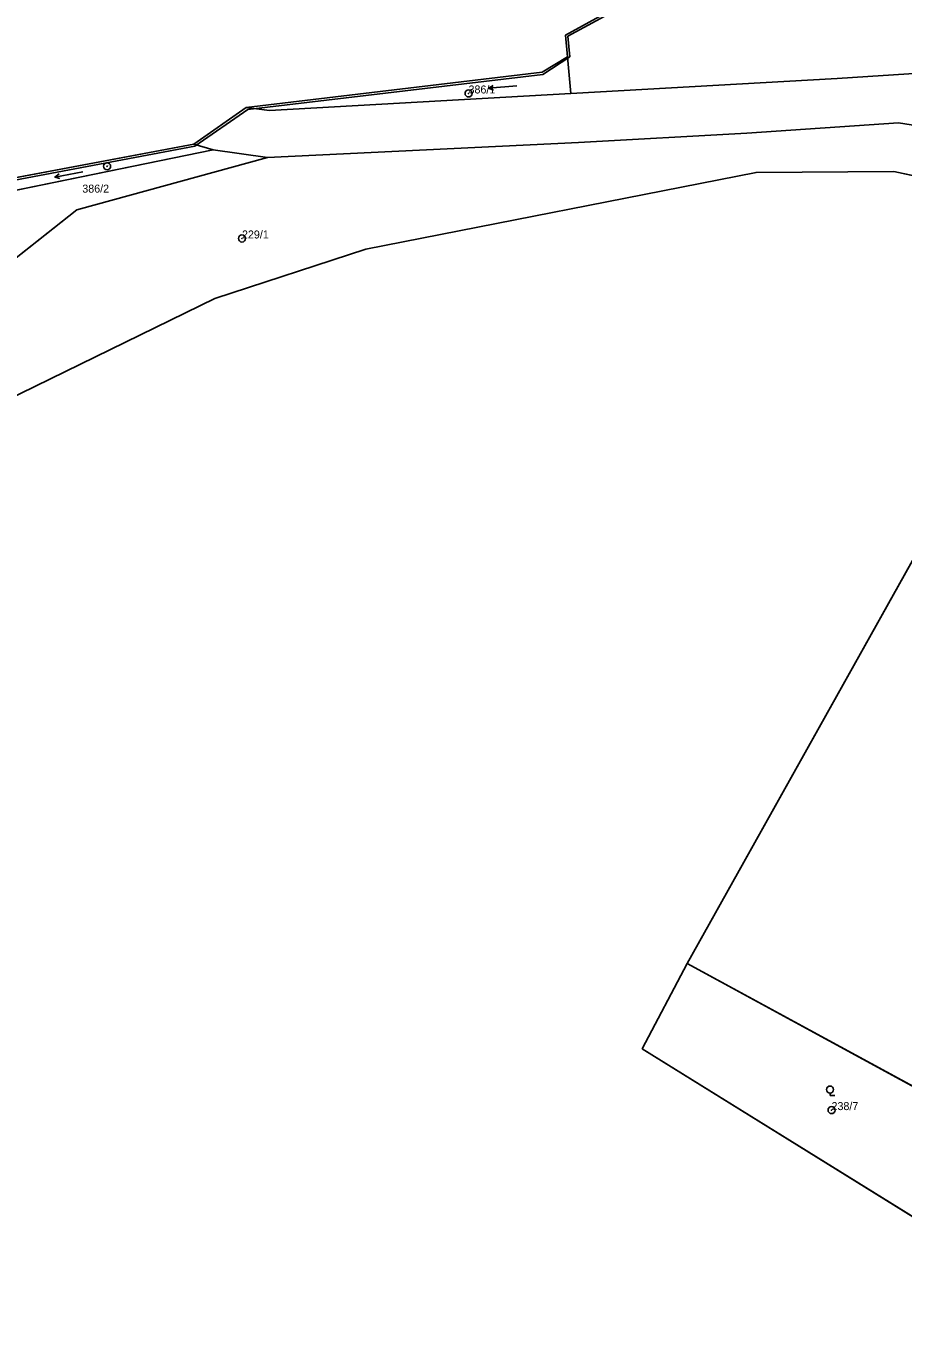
# Model space of a CAD drawing. Extents: x -652854 to -650068, y -1097661 to -1095417.
# Drawn here: x -651296.9 to -651110.6, y -1096137.1 to -1095861.8 of the extents above; entities that cross this region are included whole.
import ezdxf

# ---------------------------------------------------------------- set-up
doc = ezdxf.new("R2010")
doc.units = 0
for name, color, linetype in [('Definiční body parcel', 7, 'Continuous'), ('Hranice obcí', 7, 'Continuous'), ('Hranice parcel', 7, 'Continuous'), ('Obvody jako plochy', 7, 'Continuous'), ('Ostatní hranice', 7, 'Continuous'), ('Parcelní čísla', 7, 'Continuous'), ('Prvky pro prodl_ par_ č_', 7, 'Continuous'), ('Značky kultur', 7, 'Continuous')]:
    doc.layers.add(name, color=color, linetype=linetype)

msp = doc.modelspace()

# ---------------------------------------------------------------- linework, layer by layer
at = {"layer": 'Definiční body parcel'}
for centre, radius in [((-651202.86, -1095876.12), 0.75), ((-651202.86, -1095876.12), 0.0327), ((-651279.63, -1095891.58), 0.75), ((-651279.63, -1095891.58), 0.0327), ((-651250.98, -1095906.92), 0.75), ((-651250.98, -1095906.92), 0.0327), ((-651125.76, -1096092.04), 0.75), ((-651125.76, -1096092.04), 0.0327)]:
    msp.add_circle(centre, radius, dxfattribs=at)
at = {"layer": 'Hranice obcí'}
for p, q in [((-651182.24, -1095863.72), (-651170.03, -1095857.03)), ((-651181.83, -1095868.33), (-651182.24, -1095863.72)), ((-651187.22, -1095871.58), (-651181.83, -1095868.33)), ((-651250.06, -1095879.13), (-651187.22, -1095871.58)), ((-651261.23, -1095886.87), (-651250.06, -1095879.13)), ((-651306.87, -1095895.47), (-651261.23, -1095886.87))]:
    msp.add_line(p, q, dxfattribs=at)
at = {"layer": 'Hranice parcel'}
for p, q in [((-651181.14, -1095876.14), (-651181.83, -1095868.33)), ((-651181.14, -1095876.14), (-651124.53, -1095872.94)), ((-651124.53, -1095872.94), (-651106.05, -1095871.75)), ((-651245.11, -1095879.76), (-651181.14, -1095876.14)), ((-651250.06, -1095879.13), (-651245.11, -1095879.76)), ((-651143.77, -1095884.53), (-651111.53, -1095882.37)), ((-651111.53, -1095882.37), (-651098.01, -1095884.51)), ((-651179.53, -1095886.51), (-651143.77, -1095884.53)), ((-651304.11, -1095897.7), (-651257.1, -1095888.1)), ((-651261.23, -1095886.87), (-651257.1, -1095888.1)), ((-651257.1, -1095888.1), (-651245.57, -1095889.73)), ((-651245.57, -1095889.73), (-651179.53, -1095886.51)), ((-651245.57, -1095889.73), (-651286.04, -1095900.87)), ((-651141.79, -1095892.88), (-651224.65, -1095909.2)), ((-651112.56, -1095892.68), (-651141.79, -1095892.88)), ((-651086.96, -1095898.16), (-651112.56, -1095892.68)), ((-651326.79, -1095933.01), (-651286.04, -1095900.87)), ((-651224.65, -1095909.2), (-651256.73, -1095919.7)), ((-651256.73, -1095919.7), (-651301.18, -1095941.4)), ((-651099.24, -1095958.6), (-651156.45, -1096060.87)), ((-651156.45, -1096060.87), (-651165.97, -1096079.02)), ((-651156.45, -1096060.87), (-651088.94, -1096097.65)), ((-651165.97, -1096079.02), (-651097.64, -1096121.44))]:
    msp.add_line(p, q, dxfattribs=at)
at = {"layer": 'Obvody jako plochy'}
for points in [[(-651124.53, -1095872.94), (-651106.05, -1095871.75), (-651093.24, -1095871.75), (-651090.63, -1095871.34), (-651091.53, -1095855.39), (-651091.66, -1095853.64), (-651099.73, -1095851.59), (-651143.81, -1095850.45), (-651170.03, -1095857.03), (-651182.24, -1095863.72), (-651181.83, -1095868.33), (-651181.14, -1095876.14)], [(-651250.06, -1095879.13), (-651245.11, -1095879.76), (-651181.14, -1095876.14), (-651181.83, -1095868.33), (-651187.22, -1095871.58)], [(-651261.23, -1095886.87), (-651306.87, -1095895.47), (-651304.11, -1095897.7), (-651257.1, -1095888.1)], [(-651156.45, -1096060.87), (-651165.97, -1096079.02), (-651097.64, -1096121.44), (-651087.49, -1096100.27), (-651089.62, -1096099.14), (-651088.94, -1096097.65)]]:
    msp.add_lwpolyline(points, close=True, dxfattribs=at)
for points in [[(-651106.05, -1095871.75), (-651124.53, -1095872.94), (-651181.14, -1095876.14), (-651245.11, -1095879.76), (-651250.06, -1095879.13), (-651261.23, -1095886.87), (-651257.1, -1095888.1), (-651245.57, -1095889.73), (-651179.53, -1095886.51), (-651143.77, -1095884.53), (-651111.53, -1095882.37), (-651098.01, -1095884.51)], [(-651301.18, -1095941.4), (-651256.73, -1095919.7), (-651224.65, -1095909.2), (-651141.79, -1095892.88), (-651112.56, -1095892.68), (-651086.96, -1095898.16), (-651066.45, -1095946.35), (-651049.83, -1095974.3), (-651042.95, -1095978.23), (-651041.27, -1095975.19), (-651039.04, -1095970.98), (-651041.17, -1095970.17), (-651056.46, -1095938.68), (-651079.41, -1095896.61), (-651098.01, -1095884.51), (-651111.53, -1095882.37), (-651143.77, -1095884.53), (-651179.53, -1095886.51), (-651245.57, -1095889.73), (-651286.04, -1095900.87), (-651326.79, -1095933.01)], [(-651326.79, -1095933.01), (-651286.04, -1095900.87), (-651245.57, -1095889.73), (-651257.1, -1095888.1), (-651304.11, -1095897.7)], [(-650933.62, -1096190.95), (-650913.45, -1096134.6), (-650990.95, -1096076.09), (-651009.35, -1096106.79), (-651010.55, -1096105.82), (-651030.5, -1096133.13), (-651070.99, -1096111.17), (-651084.01, -1096101.86), (-651087.49, -1096100.27), (-651097.64, -1096121.44), (-651165.97, -1096079.02), (-651156.45, -1096060.87), (-651099.24, -1095958.6), (-651062.2, -1095980.68), (-651049.83, -1095974.3), (-651066.45, -1095946.35), (-651086.96, -1095898.16), (-651112.56, -1095892.68), (-651141.79, -1095892.88), (-651224.65, -1095909.2), (-651256.73, -1095919.7), (-651301.18, -1095941.4)], [(-651099.24, -1095958.6), (-651156.45, -1096060.87), (-651088.94, -1096097.65)]]:
    msp.add_lwpolyline(points, dxfattribs=at)
at = {"layer": 'Ostatní hranice'}
for p, q in [((-651181.78, -1095863.92), (-651169.75, -1095857.45)), ((-651181.33, -1095868.35), (-651181.78, -1095863.92)), ((-651187.08, -1095872.07), (-651181.33, -1095868.35)), ((-651249.75, -1095879.54), (-651187.08, -1095872.07)), ((-651260.97, -1095887.31), (-651249.75, -1095879.54)), ((-651306.96, -1095895.96), (-651260.97, -1095887.31))]:
    msp.add_line(p, q, dxfattribs=at)
at = {"layer": 'Značky kultur'}
for p, q in [((-651192.618, -1095874.527), (-651198.602, -1095874.973)), ((-651284.811, -1095892.767), (-651290.709, -1095893.873)), ((-651126.07, -1096088.43), (-651126.07, -1096088.93)), ((-651126.07, -1096088.93), (-651125.047, -1096088.93))]:
    msp.add_line(p, q, dxfattribs=at)
for points in [[(-651197.567, -1095875.397), (-651198.602, -1095874.973), (-651197.642, -1095874.4)], [(-651289.633, -1095894.18), (-651290.709, -1095893.873), (-651289.818, -1095893.197)]]:
    msp.add_lwpolyline(points, dxfattribs=at)
msp.add_circle((-651126.07, -1096087.68), 0.75, dxfattribs=at)

# ---------------------------------------------------------------- texts
at = {"layer": 'Parcelní čísla'}
for s, p in [('386/1', (-651202.86, -1095876.12)), ('229/1', (-651250.98, -1095906.92)), ('238/7', (-651125.76, -1096092.04))]:
    msp.add_text(s, height=1.7, dxfattribs=at).set_placement(p)
msp.add_text('386/2', height=0.1, rotation=12.807, dxfattribs=at).set_placement((-651279.63, -1095891.58))
at = {"layer": 'Prvky pro prodl_ par_ č_'}
msp.add_text('386/2', height=1.7, dxfattribs=at).set_placement((-651284.898, -1095897.18))

doc.saveas('drawing.dxf')
